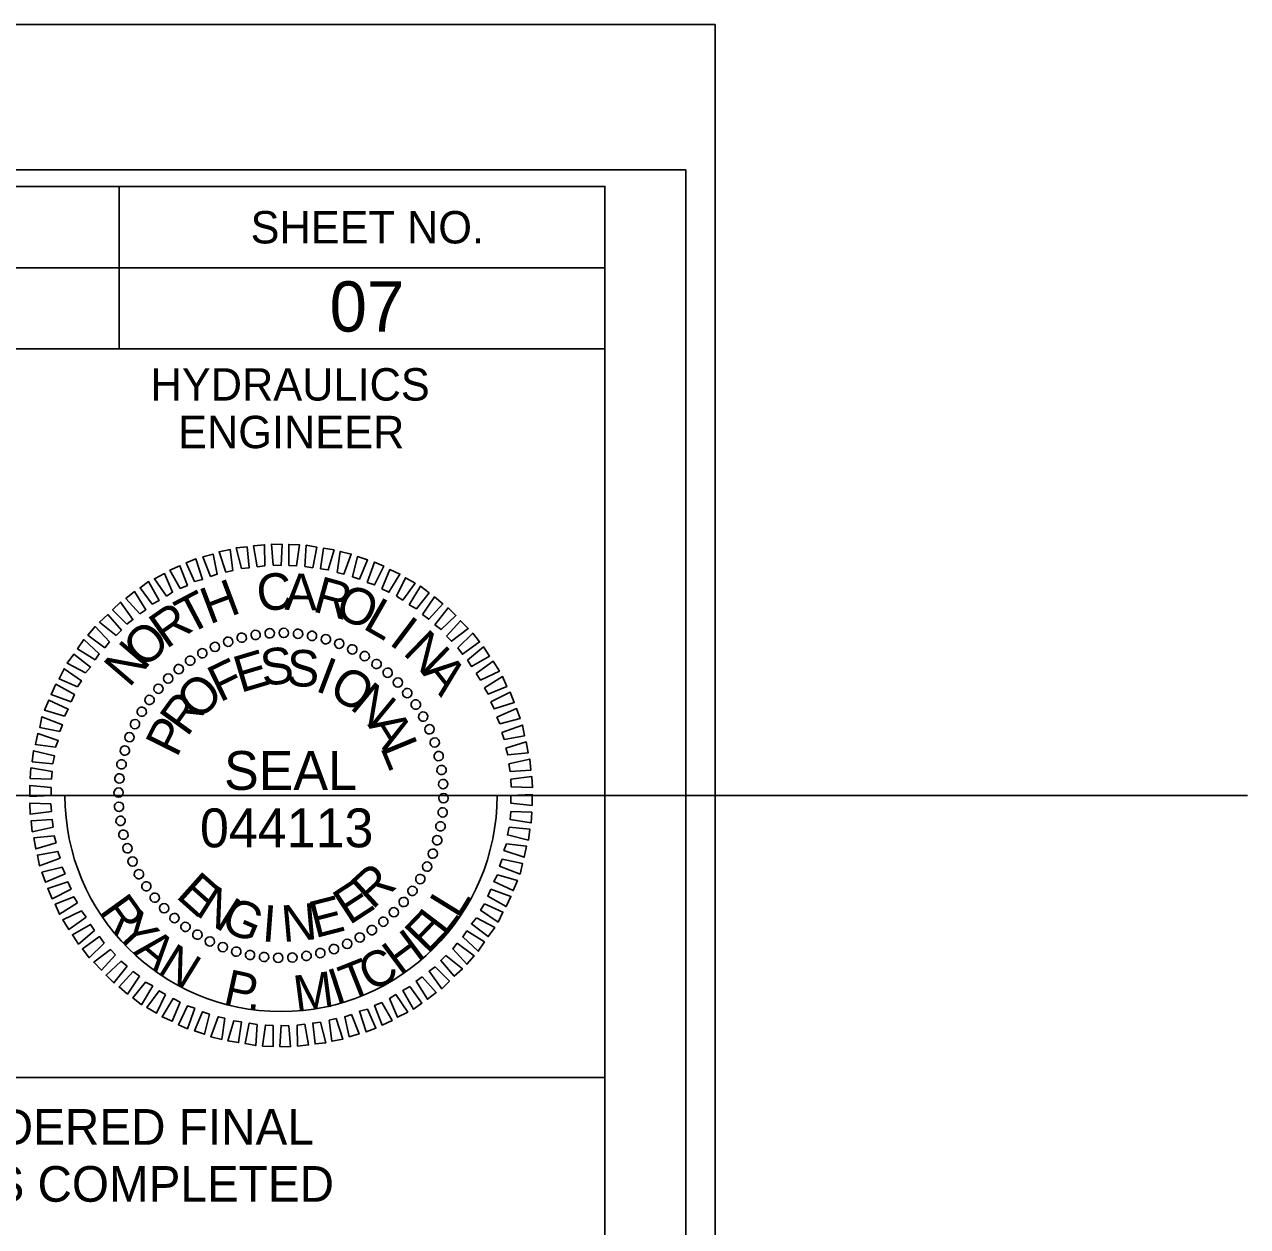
# Model space of a CAD drawing. Extents: x 1260839 to 1262605, y 747346 to 748446.
# Drawn here: x 1262416.1 to 1262604.9, y 748260.2 to 748445.7 of the extents above; entities that cross this region are included whole.
import ezdxf

# ---------------------------------------------------------------- set-up
doc = ezdxf.new("R2010")
doc.units = 0
for name, color, linetype in [('Prop Drainage Structure Bridge', 7, 'Continuous'), ('Prop Drainage Structure Bridge Opening', 7, 'Continuous'), ('Prop Grid Mask', 7, 'Continuous'), ('Prop Horizontal Alignment', 7, 'Continuous'), ('Prop Paved Shoulder', 7, 'Continuous'), ('Prop Terminator CELL', 7, 'Continuous'), ('Prop VPI Label', 7, 'Continuous'), ('Sheet Border Standard 30in CELL', 7, 'Continuous'), ('Sheet Layout Plan Border', 7, 'Continuous')]:
    doc.layers.add(name, color=color, linetype=linetype)

msp = doc.modelspace()

# ---------------------------------------------------------------- linework, layer by layer
at = {"layer": 'Prop Drainage Structure Bridge'}
for p, q in [((1262454, 748351.8), (1262454, 748351.8)), ((1262456.2, 748351.85), (1262456.2, 748351.85)), ((1262458.4, 748351.7), (1262458.4, 748351.7)), ((1262445.55, 748349.7), (1262445.55, 748349.7)), ((1262447.55, 748350.5), (1262447.55, 748350.5)), ((1262449.65, 748351.1), (1262449.65, 748351.1)), ((1262451.85, 748351.5), (1262451.85, 748351.5)), ((1262460.55, 748351.35), (1262460.55, 748351.35)), ((1262462.65, 748350.9), (1262462.65, 748350.9)), ((1262464.75, 748350.2), (1262464.75, 748350.2)), ((1262443.6, 748348.7), (1262443.6, 748348.7)), ((1262466.75, 748349.3), (1262466.75, 748349.3)), ((1262468.7, 748348.3), (1262468.7, 748348.3)), ((1262439.95, 748346.3), (1262439.95, 748346.3)), ((1262441.7, 748347.55), (1262441.7, 748347.55)), ((1262470.5, 748347.05), (1262470.5, 748347.05)), ((1262438.3, 748344.8), (1262438.3, 748344.8)), ((1262472.25, 748345.7), (1262472.25, 748345.7)), ((1262473.8, 748344.2), (1262473.8, 748344.2)), ((1262436.8, 748343.25), (1262436.8, 748343.25)), ((1262475.3, 748342.55), (1262475.3, 748342.55)), ((1262435.45, 748341.5), (1262435.45, 748341.5)), ((1262476.55, 748340.8), (1262476.55, 748340.8)), ((1262434.2, 748339.7), (1262434.2, 748339.7)), ((1262477.7, 748338.9), (1262477.7, 748338.9)), ((1262433.2, 748337.75), (1262433.2, 748337.75)), ((1262478.7, 748336.95), (1262478.7, 748336.95)), ((1262432.3, 748335.75), (1262432.3, 748335.75)), ((1262479.5, 748334.95), (1262479.5, 748334.95)), ((1262431.6, 748333.65), (1262431.6, 748333.65)), ((1262480.1, 748332.85), (1262480.1, 748332.85)), ((1262431.15, 748331.55), (1262431.15, 748331.55)), ((1262430.8, 748329.4), (1262430.8, 748329.4)), ((1262480.5, 748330.65), (1262480.5, 748330.65)), ((1262430.65, 748327.2), (1262430.65, 748327.2)), ((1262480.8, 748328.5), (1262480.8, 748328.5)), ((1262455.75, 748326.75), (1262455.75, 748326.75)), ((1262480.85, 748326.3), (1262480.85, 748326.3)), ((1262430.7, 748325), (1262430.7, 748325)), ((1262480.7, 748324.1), (1262480.7, 748324.1)), ((1262431, 748322.85), (1262431, 748322.85)), ((1262480.35, 748321.95), (1262480.35, 748321.95)), ((1262431.4, 748320.65), (1262431.4, 748320.65)), ((1262479.9, 748319.85), (1262479.9, 748319.85)), ((1262432, 748318.55), (1262432, 748318.55)), ((1262479.2, 748317.75), (1262479.2, 748317.75)), ((1262432.8, 748316.55), (1262432.8, 748316.55)), ((1262478.3, 748315.75), (1262478.3, 748315.75)), ((1262433.8, 748314.6), (1262433.8, 748314.6)), ((1262434.95, 748312.7), (1262434.95, 748312.7)), ((1262476.05, 748312), (1262476.05, 748312)), ((1262477.3, 748313.8), (1262477.3, 748313.8)), ((1262436.2, 748310.95), (1262436.2, 748310.95)), ((1262474.7, 748310.25), (1262474.7, 748310.25)), ((1262437.7, 748309.3), (1262437.7, 748309.3)), ((1262473.2, 748308.7), (1262473.2, 748308.7)), ((1262439.25, 748307.8), (1262439.25, 748307.8)), ((1262441, 748306.45), (1262441, 748306.45)), ((1262471.55, 748307.2), (1262471.55, 748307.2)), ((1262442.8, 748305.2), (1262442.8, 748305.2)), ((1262467.9, 748304.8), (1262467.9, 748304.8)), ((1262469.8, 748305.95), (1262469.8, 748305.95)), ((1262444.75, 748304.2), (1262444.75, 748304.2)), ((1262446.75, 748303.3), (1262446.75, 748303.3)), ((1262448.85, 748302.6), (1262448.85, 748302.6)), ((1262463.95, 748303), (1262463.95, 748303)), ((1262465.95, 748303.8), (1262465.95, 748303.8)), ((1262450.95, 748302.15), (1262450.95, 748302.15)), ((1262453.1, 748301.8), (1262453.1, 748301.8)), ((1262455.3, 748301.65), (1262455.3, 748301.65)), ((1262457.5, 748301.7), (1262457.5, 748301.7)), ((1262459.65, 748302), (1262459.65, 748302)), ((1262461.85, 748302.4), (1262461.85, 748302.4))]:
    msp.add_line(p, q, dxfattribs=at)
for points in [[(1262449.65, 748361.75), (1262448.85, 748364.95), (1262450.5, 748365.1), (1262450.85, 748361.9)], [(1262452.05, 748362.05), (1262451.5, 748365.25), (1262453.2, 748365.45), (1262453.25, 748362.2)], [(1262454.55, 748362.3), (1262454.3, 748365.55), (1262455.95, 748365.5), (1262455.75, 748362.25)], [(1262456.95, 748362.25), (1262456.95, 748365.5), (1262458.6, 748365.45), (1262458.15, 748362.2)], [(1262459.45, 748362.1), (1262459.65, 748365.35), (1262461.3, 748365.05), (1262460.65, 748361.9)], [(1262461.85, 748361.7), (1262462.3, 748364.9), (1262463.95, 748364.65), (1262463.05, 748361.55)], [(1262442.4, 748359.75), (1262441.1, 748362.65), (1262442.6, 748363.25), (1262443.65, 748360.05)], [(1262444.85, 748360.55), (1262443.7, 748363.55), (1262445.25, 748364), (1262445.9, 748360.9)], [(1262447.25, 748361.2), (1262446.2, 748364.35), (1262447.9, 748364.7), (1262448.3, 748361.45)], [(1262464.4, 748361.15), (1262464.9, 748364.4), (1262466.6, 748364), (1262465.45, 748360.9)], [(1262466.8, 748360.5), (1262467.55, 748363.6), (1262469.1, 748363.1), (1262467.85, 748360.15)], [(1262440.2, 748358.7), (1262438.6, 748361.5), (1262440.15, 748362.2), (1262441.3, 748359.15)], [(1262469.05, 748359.6), (1262470.2, 748362.75), (1262471.6, 748362.15), (1262470.2, 748359.25)], [(1262471.3, 748358.65), (1262472.55, 748361.6), (1262474.1, 748360.9), (1262472.4, 748358.1)], [(1262435.85, 748356.25), (1262434, 748358.8), (1262435.3, 748359.75), (1262436.95, 748356.85)], [(1262438.05, 748357.5), (1262436.2, 748360.2), (1262437.75, 748361), (1262439, 748358.1)], [(1262473.6, 748357.5), (1262474.95, 748360.35), (1262476.45, 748359.5), (1262474.55, 748356.9)], [(1262433.95, 748354.75), (1262431.8, 748357.15), (1262433.15, 748358.2), (1262434.9, 748355.4)], [(1262475.55, 748356.15), (1262477.3, 748359.05), (1262478.6, 748358), (1262476.65, 748355.55)], [(1262477.6, 748354.65), (1262479.45, 748357.4), (1262480.75, 748356.3), (1262478.55, 748353.95)], [(1262431.95, 748353.2), (1262429.75, 748355.4), (1262430.95, 748356.6), (1262432.9, 748353.9)], [(1262479.5, 748353.1), (1262481.55, 748355.7), (1262482.75, 748354.5), (1262480.45, 748352.35)], [(1262430.3, 748351.45), (1262427.75, 748353.5), (1262429, 748354.65), (1262431.1, 748352.25)], [(1262481.3, 748351.35), (1262483.45, 748353.7), (1262484.65, 748352.5), (1262482.05, 748350.55)], [(1262428.55, 748349.55), (1262425.95, 748351.5), (1262427.05, 748352.8), (1262429.25, 748350.45)], [(1262483.05, 748349.55), (1262485.35, 748351.8), (1262486.4, 748350.45), (1262483.75, 748348.55)], [(1262427.05, 748347.65), (1262424.35, 748349.35), (1262425.3, 748350.8), (1262427.7, 748348.6)], [(1262484.55, 748347.6), (1262487, 748349.7), (1262487.95, 748348.25), (1262485.15, 748346.65)], [(1262425.55, 748345.65), (1262422.75, 748347.15), (1262423.75, 748348.55), (1262426.35, 748346.55)], [(1262424.35, 748343.5), (1262421.5, 748344.75), (1262422.25, 748346.3), (1262424.95, 748344.45)], [(1262485.85, 748345.55), (1262488.5, 748347.45), (1262489.45, 748345.95), (1262486.55, 748344.55)], [(1262487.15, 748343.35), (1262489.95, 748345.1), (1262490.6, 748343.55), (1262487.75, 748342.4)], [(1262423.35, 748341.2), (1262420.25, 748342.35), (1262421, 748343.9), (1262423.85, 748342.3)], [(1262488.15, 748341.2), (1262491.1, 748342.7), (1262491.75, 748341.1), (1262488.65, 748340.1)], [(1262422.35, 748339), (1262419.25, 748339.9), (1262419.9, 748341.45), (1262422.9, 748340.05)], [(1262421.6, 748336.6), (1262418.5, 748337.25), (1262418.85, 748338.9), (1262422, 748337.65)], [(1262489.05, 748338.85), (1262492.1, 748340.15), (1262492.65, 748338.6), (1262489.55, 748337.8)], [(1262489.85, 748336.45), (1262493.05, 748337.6), (1262493.35, 748335.95), (1262490.2, 748335.4)], [(1262420.95, 748334.2), (1262417.85, 748334.6), (1262418.2, 748336.3), (1262421.35, 748335.25)], [(1262490.45, 748334.05), (1262493.6, 748335), (1262493.9, 748333.3), (1262490.75, 748333)], [(1262420.55, 748331.65), (1262417.35, 748331.95), (1262417.55, 748333.65), (1262420.8, 748332.85)], [(1262420.3, 748329.25), (1262417.05, 748329.35), (1262417.15, 748331), (1262420.4, 748330.45)], [(1262490.9, 748331.65), (1262494.15, 748332.35), (1262494.3, 748330.65), (1262491.1, 748330.45)], [(1262491.2, 748329.25), (1262494.45, 748329.65), (1262494.55, 748327.95), (1262491.3, 748328.05)], [(1262420.25, 748326.75), (1262417, 748326.6), (1262417, 748328.3), (1262420.25, 748327.95)], [(1262420.3, 748324.25), (1262417.05, 748323.85), (1262416.95, 748325.55), (1262420.2, 748325.45)], [(1262491.25, 748326.75), (1262494.5, 748326.9), (1262494.5, 748325.2), (1262491.25, 748325.55)], [(1262491.2, 748324.25), (1262494.45, 748324.15), (1262494.35, 748322.5), (1262491.1, 748323.05)], [(1262420.6, 748321.85), (1262417.35, 748321.15), (1262417.2, 748322.85), (1262420.4, 748323.05)], [(1262490.95, 748321.85), (1262494.15, 748321.55), (1262493.95, 748319.85), (1262490.7, 748320.65)], [(1262421.05, 748319.45), (1262417.9, 748318.5), (1262417.6, 748320.2), (1262420.75, 748320.5)], [(1262421.65, 748317.05), (1262418.45, 748315.9), (1262418.15, 748317.55), (1262421.3, 748318.1)], [(1262490.55, 748319.3), (1262493.65, 748318.9), (1262493.3, 748317.2), (1262490.15, 748318.25)], [(1262489.9, 748316.9), (1262493, 748316.25), (1262492.65, 748314.6), (1262489.5, 748315.85)], [(1262422.45, 748314.65), (1262419.4, 748313.35), (1262418.85, 748314.9), (1262421.95, 748315.7)], [(1262489.15, 748314.5), (1262492.25, 748313.6), (1262491.6, 748312.05), (1262488.6, 748313.45)], [(1262423.35, 748312.3), (1262420.4, 748310.8), (1262419.75, 748312.4), (1262422.85, 748313.4)], [(1262488.15, 748312.3), (1262491.25, 748311.15), (1262490.5, 748309.6), (1262487.65, 748311.2)], [(1262424.35, 748310.15), (1262421.55, 748308.4), (1262420.9, 748309.95), (1262423.75, 748311.1)], [(1262425.65, 748307.95), (1262423, 748306.05), (1262422.05, 748307.55), (1262424.95, 748308.95)], [(1262487.15, 748310), (1262490, 748308.75), (1262489.25, 748307.2), (1262486.55, 748309.05)], [(1262426.95, 748305.9), (1262424.5, 748303.8), (1262423.55, 748305.25), (1262426.35, 748306.85)], [(1262485.95, 748307.85), (1262488.75, 748306.35), (1262487.75, 748304.95), (1262485.15, 748306.95)], [(1262428.45, 748303.95), (1262426.15, 748301.7), (1262425.1, 748303.05), (1262427.75, 748304.95)], [(1262484.45, 748305.85), (1262487.15, 748304.15), (1262486.2, 748302.7), (1262483.8, 748304.9)], [(1262430.2, 748302.15), (1262428.05, 748299.8), (1262426.85, 748301), (1262429.45, 748302.95)], [(1262482.95, 748303.95), (1262485.55, 748302), (1262484.45, 748300.7), (1262482.25, 748303.05)], [(1262432, 748300.4), (1262429.95, 748297.8), (1262428.75, 748299), (1262431.05, 748301.15)], [(1262481.2, 748302.05), (1262483.75, 748300), (1262482.5, 748298.85), (1262480.4, 748301.25)], [(1262433.9, 748298.85), (1262432.05, 748296.1), (1262430.75, 748297.2), (1262432.95, 748299.55)], [(1262477.55, 748298.75), (1262479.7, 748296.35), (1262478.35, 748295.3), (1262476.6, 748298.1)], [(1262479.55, 748300.3), (1262481.75, 748298.1), (1262480.55, 748296.9), (1262478.6, 748299.6)], [(1262435.95, 748297.35), (1262434.2, 748294.45), (1262432.9, 748295.5), (1262434.85, 748297.95)], [(1262475.65, 748297.25), (1262477.5, 748294.7), (1262476.2, 748293.75), (1262474.55, 748296.65)], [(1262437.9, 748296), (1262436.55, 748293.15), (1262435.05, 748294), (1262436.95, 748296.6)], [(1262440.2, 748294.85), (1262438.95, 748291.9), (1262437.4, 748292.6), (1262439.1, 748295.4)], [(1262473.45, 748296), (1262475.3, 748293.3), (1262473.75, 748292.5), (1262472.5, 748295.4)], [(1262442.45, 748293.9), (1262441.3, 748290.75), (1262439.9, 748291.35), (1262441.3, 748294.25)], [(1262444.7, 748293), (1262443.95, 748289.9), (1262442.4, 748290.4), (1262443.65, 748293.35)], [(1262469.1, 748293.75), (1262470.4, 748290.85), (1262468.9, 748290.25), (1262467.85, 748293.45)], [(1262471.3, 748294.8), (1262472.9, 748292), (1262471.35, 748291.3), (1262470.2, 748294.35)], [(1262447.1, 748292.35), (1262446.6, 748289.1), (1262444.9, 748289.5), (1262446.05, 748292.6)], [(1262449.65, 748291.8), (1262449.2, 748288.6), (1262447.55, 748288.85), (1262448.45, 748291.95)], [(1262452.05, 748291.4), (1262451.85, 748288.15), (1262450.2, 748288.45), (1262450.85, 748291.6)], [(1262454.55, 748291.25), (1262454.55, 748288), (1262452.9, 748288.05), (1262453.35, 748291.3)], [(1262456.95, 748291.2), (1262457.2, 748287.95), (1262455.55, 748288), (1262455.75, 748291.25)], [(1262459.45, 748291.45), (1262460, 748288.25), (1262458.3, 748288.05), (1262458.25, 748291.3)], [(1262461.85, 748291.75), (1262462.65, 748288.55), (1262461, 748288.4), (1262460.65, 748291.6)], [(1262464.25, 748292.3), (1262465.3, 748289.15), (1262463.6, 748288.8), (1262463.2, 748292.05)], [(1262466.65, 748292.95), (1262467.8, 748289.95), (1262466.25, 748289.5), (1262465.6, 748292.6)]]:
    msp.add_lwpolyline(points, close=True, dxfattribs=at)
for centre, major_axis in [((1262449.69, 748351.09), (-0.174, 0.699)), ((1262451.83, 748351.52), (-0.113, 0.711)), ((1262454, 748351.77), (-0.05, 0.718)), ((1262456.19, 748351.83), (0.013, 0.72)), ((1262458.38, 748351.7), (0.075, 0.716)), ((1262460.54, 748351.37), (0.137, 0.707)), ((1262462.67, 748350.86), (0.198, 0.692)), ((1262445.55, 748349.66), (-0.293, 0.658)), ((1262447.59, 748350.47), (-0.234, 0.681)), ((1262464.74, 748350.17), (0.258, 0.672)), ((1262466.75, 748349.29), (0.316, 0.647)), ((1262441.73, 748347.55), (-0.403, 0.597)), ((1262443.6, 748348.69), (-0.349, 0.63)), ((1262468.67, 748348.25), (0.371, 0.617)), ((1262470.5, 748347.04), (0.423, 0.582)), ((1262439.97, 748346.24), (-0.453, 0.56)), ((1262472.21, 748345.68), (0.472, 0.543)), ((1262438.33, 748344.79), (-0.5, 0.518)), ((1262473.8, 748344.17), (0.518, 0.5)), ((1262435.46, 748341.49), (-0.582, 0.423)), ((1262436.83, 748343.21), (-0.543, 0.472)), ((1262475.24, 748342.54), (0.56, 0.453)), ((1262434.26, 748339.67), (-0.617, 0.371)), ((1262476.55, 748340.78), (0.597, 0.403)), ((1262433.21, 748337.75), (-0.647, 0.316)), ((1262477.69, 748338.91), (0.63, 0.349)), ((1262432.34, 748335.74), (-0.672, 0.258)), ((1262478.67, 748336.95), (0.658, 0.293)), ((1262479.47, 748334.92), (0.681, 0.234)), ((1262431.65, 748333.67), (-0.692, 0.198)), ((1262480.09, 748332.82), (0.699, 0.174)), ((1262431.13, 748331.54), (-0.707, 0.137)), ((1262480.53, 748330.68), (0.711, 0.113)), ((1262430.81, 748329.37), (-0.716, 0.075)), ((1262480.77, 748328.5), (0.718, 0.05)), ((1262430.68, 748327.19), (-0.72, 0.013)), ((1262430.74, 748325), (-0.718, -0.05)), ((1262480.83, 748326.32), (0.72, -0.013)), ((1262430.98, 748322.83), (-0.711, -0.113)), ((1262480.7, 748324.13), (0.716, -0.075)), ((1262431.42, 748320.69), (-0.699, -0.174)), ((1262480.37, 748321.97), (0.707, -0.137)), ((1262479.86, 748319.84), (0.692, -0.198)), ((1262432.04, 748318.59), (-0.681, -0.234)), ((1262479.17, 748317.76), (0.672, -0.258)), ((1262432.84, 748316.55), (-0.658, -0.293)), ((1262478.3, 748315.76), (0.647, -0.316)), ((1262433.82, 748314.59), (-0.63, -0.349)), ((1262477.25, 748313.84), (0.617, -0.371)), ((1262434.96, 748312.73), (-0.597, -0.403)), ((1262476.04, 748312.01), (0.582, -0.423)), ((1262436.26, 748310.97), (-0.56, -0.453)), ((1262437.71, 748309.33), (-0.518, -0.5)), ((1262474.68, 748310.3), (0.543, -0.472)), ((1262439.3, 748307.82), (-0.472, -0.543)), ((1262473.18, 748308.71), (0.5, -0.518)), ((1262441.01, 748306.46), (-0.423, -0.582)), ((1262469.78, 748305.96), (0.403, -0.597)), ((1262471.54, 748307.26), (0.453, -0.56)), ((1262442.84, 748305.26), (-0.371, -0.617)), ((1262444.76, 748304.21), (-0.316, -0.647)), ((1262465.96, 748303.84), (0.293, -0.658)), ((1262467.91, 748304.82), (0.349, -0.63)), ((1262446.77, 748303.34), (-0.258, -0.672)), ((1262448.84, 748302.64), (-0.198, -0.692)), ((1262450.97, 748302.13), (-0.137, -0.707)), ((1262453.13, 748301.81), (-0.075, -0.716)), ((1262459.68, 748301.98), (0.113, -0.711)), ((1262461.82, 748302.42), (0.174, -0.699)), ((1262463.92, 748303.04), (0.234, -0.681)), ((1262455.32, 748301.68), (-0.013, -0.72)), ((1262457.5, 748301.73), (0.05, -0.718))]:
    msp.add_ellipse(centre, major_axis=major_axis, ratio=0.999708, dxfattribs=at)
at = {"layer": 'Prop Drainage Structure Bridge Opening'}
msp.add_line((1262522.75, 748445.74), (1260838.75, 748445.74), dxfattribs=at)
at = {"layer": 'Prop Grid Mask'}
msp.add_line((1262355.7, 748326.75), (1262604.94, 748326.75), dxfattribs=at)
at = {"layer": 'Prop Horizontal Alignment'}
msp.add_arc((1262455.75, 748326.75), 33.36, 180, 360, dxfattribs=at)
at = {"layer": 'Prop Paved Shoulder'}
for p, q in [((1262430.75, 748420.69), (1262430.75, 748395.69)), ((1262305.7, 748408.19), (1262505.75, 748408.19))]:
    msp.add_line(p, q, dxfattribs=at)
for points in [[(1262505.75, 748420.74), (1261005.75, 748420.74), (1261005.75, 747370.74), (1262505.75, 747370.74)], [(1262305.7, 748420.74), (1262505.75, 748420.74), (1262505.75, 748395.69), (1262305.7, 748395.69)], [(1262405.75, 748395.69), (1262505.75, 748395.69), (1262505.75, 748283.19), (1262405.75, 748283.19)]]:
    msp.add_lwpolyline(points, close=True, dxfattribs=at)
at = {"layer": 'Prop Terminator CELL'}
msp.add_lwpolyline([(1262518.25, 748423.29), (1260851.75, 748423.29), (1260851.75, 747368.19), (1262518.25, 747368.19)], close=True, dxfattribs=at)
at = {"layer": 'Prop VPI Label'}
msp.add_lwpolyline([(1262522.75, 748445.74), (1260838.75, 748445.74), (1260838.75, 747345.74), (1262522.75, 747345.74)], close=True, dxfattribs=at)
at = {"layer": 'Sheet Layout Plan Border'}
for p, q in [((1262305.7, 748283.19), (1262505.74, 748283.19)), ((1262505.74, 748283.17), (1262505.74, 748259.67))]:
    msp.add_line(p, q, dxfattribs=at)

# ---------------------------------------------------------------- texts
at = {"layer": 'Prop Drainage Structure Bridge'}
for s, height, rotation, p in [('C', 5.64, 6.2199, (1262452.3, 748355.1)), ('H', 5.64, 20.6195, (1262444.7, 748353.1)), ('A', 5.64, 359.0203, (1262456.25, 748355.4)), ('R', 5.64, 344.6211, (1262460.45, 748355.2)), ('T', 5.64, 27.8198, (1262441.45, 748351.45)), ('O', 5.64, 337.4212, (1262463.8, 748354.45)), ('R', 5.64, 35.0205, (1262438.05, 748349.25)), ('L', 5.64, 330.2209, (1262468.2, 748352.6)), ('I', 5.64, 323.0201, (1262472.25, 748350.2)), ('O', 5.64, 42.2217, (1262434.6, 748346.15)), ('N', 5.64, 315.8189, (1262474.4, 748348.65)), ('N', 5.64, 49.4235, (1262432.3, 748343.25)), ('S', 5.64, 7.2556, (1262452.95, 748343.6)), ('F', 5.64, 25.967, (1262446.3, 748341.05)), ('E', 5.64, 16.6111, (1262449.5, 748342.55)), ('S', 5.64, 357.9004, (1262456.55, 748343.65)), ('I', 5.64, 339.1896, (1262460.85, 748342.95)), ('O', 5.64, 329.8335, (1262462.85, 748342.25)), ('A', 5.64, 308.6172, (1262477.35, 748345.7)), ('O', 5.64, 44.6812, (1262443, 748338.1)), ('N', 5.64, 320.4766, (1262466.2, 748340.25)), ('R', 5.64, 54.0397, (1262441.25, 748335.65)), ('P', 5.64, 63.3989, (1262439.65, 748332.45)), ('A', 5.64, 301.7603, (1262469.05, 748337.65)), ('L', 5.64, 292.4008, (1262471, 748334.2)), ('SEAL', 5.998, 360, (1262446.96, 748327.6)), ('044113', 5.998, 360, (1262443.24, 748318.74)), ('R', 5.64, 42.4814, (1262469.85, 748309)), ('E', 5.64, 318.2769, (1262439.35, 748311.1)), ('E', 5.64, 33.1241, (1262466.3, 748306.65)), ('N', 5.64, 327.634, (1262442.35, 748308.4)), ('R', 5.5, 305.8361, (1262427.53, 748308.85)), ('G', 5.64, 336.9902, (1262446.15, 748306.15)), ('N', 5.64, 5.0564, (1262456.05, 748304.1)), ('E', 5.64, 14.4118, (1262461, 748304.7)), ('L', 5.5, 58.4194, (1262483.12, 748307.56)), ('Y', 5.5, 312.7625, (1262429.89, 748305.58)), ('I', 5.64, 355.7012, (1262452.7, 748304.25)), ('E', 5.5, 46.0262, (1262478.36, 748302.14)), ('L', 5.5, 52.6092, (1262481.04, 748304.89)), ('A', 5.5, 320.0897, (1262432.8, 748302.45)), ('H', 5.5, 36.7814, (1262474.12, 748298.82)), ('N', 5.5, 328.2755, (1262436.49, 748299.43)), ('C', 5.5, 27.9087, (1262469.59, 748296.33)), ('T', 5.5, 21.6119, (1262466.17, 748294.99)), ('P', 5.5, 347.6523, (1262446.65, 748294.59)), ('M', 5.5, 7.4156, (1262458.06, 748293.41)), ('I', 5.5, 18.0915, (1262464.2, 748294.41)), ('.', 5.5, 354.2353, (1262450.4, 748293.76))]:
    msp.add_text(s, height=height, rotation=rotation, dxfattribs=at).set_placement(p)
at = {"layer": 'Prop Paved Shoulder'}
for s, p in [('SHEET NO.', (1262451.05, 748411.94)), ('HYDRAULICS', (1262435.61, 748387.69)), ('ENGINEER', (1262439.86, 748380.34))]:
    msp.add_text(s, height=5, dxfattribs=at).set_placement(p)
at = {"layer": 'Sheet Border Standard 30in CELL'}
msp.add_text('07', height=7.75, dxfattribs=at).set_placement((1262463.25, 748398.34))
at = {"layer": 'Sheet Layout Plan Border'}
for s, p in [('DOCUMENT NOT CONSIDERED FINAL', (1262326.78, 748272.84)), ('UNLESS ALL SIGNATURES COMPLETED', (1262321.7, 748264.04))]:
    msp.add_text(s, height=5.5, dxfattribs=at).set_placement(p)

doc.saveas('drawing.dxf')
